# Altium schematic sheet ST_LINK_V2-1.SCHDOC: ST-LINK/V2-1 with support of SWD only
size A4; Author: A.B; CompanyName: STMicroelectronics; Organization: Microcontrollers Division; Address1: 12, Rue Jules HOROWITZ; Address2: 38019 Grenoble; Address3: FRANCE; DocumentNumber: MB1272; Revision: A-01; SheetNumber: 15; SheetTotal: 15; Project: STM32MP15-DISCO PI
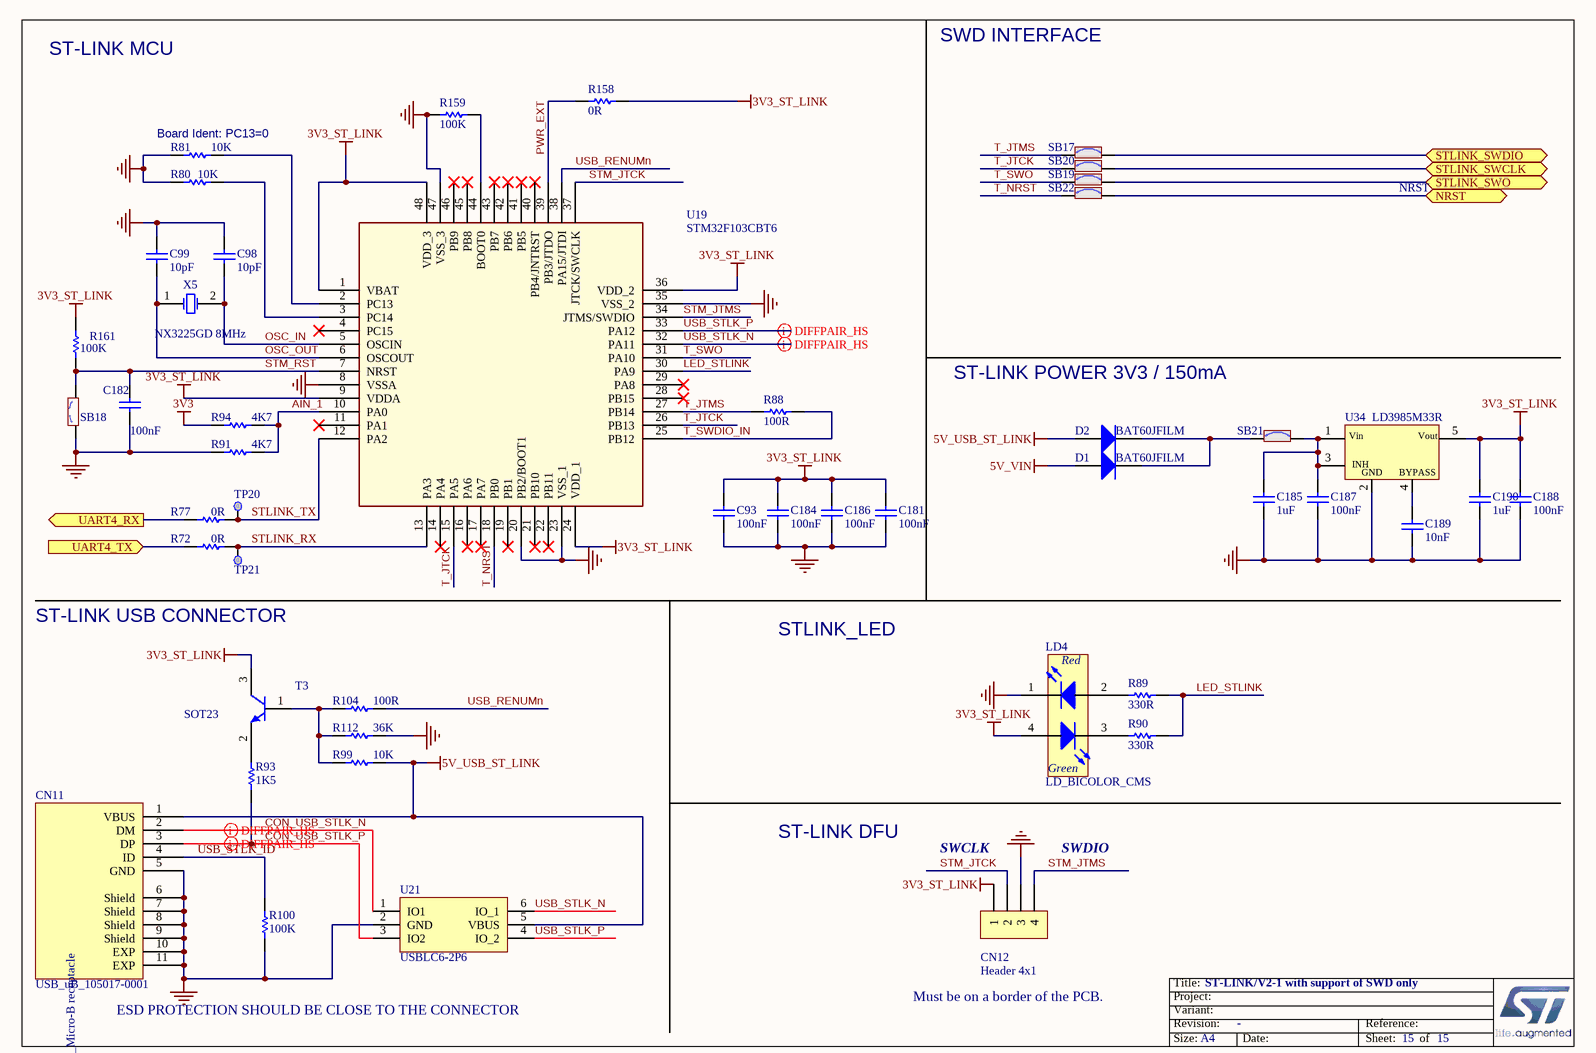
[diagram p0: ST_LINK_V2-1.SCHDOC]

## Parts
C93  value 100nF  [C0402]
C98  value 10pF  [C0402]
C99  value 10pF  [C0402]
C181  value 100nF  [C0402]
C182  value 100nF  [C0402]
C184  value 100nF  [C0402]
C185  value 1uF  [C0603]
C186  value 100nF  [C0402]
C187  value 100nF  [C0402]
C188  value 100nF  [C0402]
C189  value 10nF  [C0402]
C190  value 1uF  [C0603]
CN11  value USB_uB_105017-0001  [CON_USBMICROB_MOLEX_105017-0001_H2P90]
CN12  value Header 4x1  [CON_SAMTEC_TSW-104-07-G-S]
D1  value BAT60JFILM  [DIO_SOD323]
D2  value BAT60JFILM  [DIO_SOD323]
LD4  value LD_BICOLOR_CMS  [LED_BI-GR_HSMF-A201-A00J1]
R72  value 0R  [R0402]
R77  value 0R  [R0402]
R80  value 10K  [R0402]
R81  value 10K  [R0402]
R88  value 100R  [R0402]
R89  value 330R  [R0402]
R90  value 330R  [R0402]
R91  value 4K7  [R0402]
R93  value 1K5  [R0402]
R94  value 4K7  [R0402]
R99  value 10K  [R0402]
R100  value 100K  [R0402]
R104  value 100R  [R0402]
R112  value 36K  [R0402]
R158  value 0R  [R0402]
R159  value 100K  [R0402]
R161  value 100K  [R0402]
SB17  (no value)  [SOLDER-BRIDGE_R0603-0R]
SB18  (no value)  [SOLDER-BRIDGE_R0603-0R]
SB19  (no value)  [SOLDER-BRIDGE_R0603-0R]
SB20  (no value)  [SOLDER-BRIDGE_R0603-0R]
SB21  (no value)  [SOLDER-BRIDGE_R0603-0R]
SB22  (no value)  [SOLDER-BRIDGE_R0603-0R]
T3  value SOT23  [NPN_SOT23]
TP20  Test Point  [TP_SMD_1MM]  (value not drawn)  (no BOM)
TP21  Test Point  [TP_SMD_1MM]  (value not drawn)  (no BOM)
U19  value STM32F103CBT6  [ICC_LQFP48_7X7_P050]
U21  value USBLC6-2P6  [ESD_SOT666]
U34  value LD3985M33R  [REG_SOT23-5L]
X5  value NX3225GD 8MHz  [CRY_NX3225GD_2P]

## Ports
NRST (bidir), STLINK_SWCLK, STLINK_SWDIO, STLINK_SWO, UART4_RX (out), UART4_TX (in)

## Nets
3V3: R94.1
3V3_ST_LINK: C93.2 C181.2 C184.2 C186.2 C188.2 C190.2 CN12.1 LD4.4(YellowGreen_anode) R158.2 R161.2 T3.3(C) U19.1(VBAT) U19.9(VDDA) U19.24(VDD_1) U19.36(VDD_2) U19.48(VDD_3) U34.5(Vout)
5V_USB_ST_LINK: CN11.1(VBUS) D2.1(A) R99.1 U21.5(VBUS)
5V_VIN: D1.1(A)
GND: C93.1 C98.2 C99.2 C181.1 C182.1 C184.1 C185.2 C186.1 C187.1 C188.1 C189.1 C190.1 CN11.5(GND) CN11.6(Shield) CN11.7(Shield) CN11.8(Shield) CN11.9(Shield) CN11.10(EXP) CN11.11(EXP) CN12.3 LD4.1(RED_cathode) R80.1 R81.2 R91.1 R100.1 R112.1 R159.1 SB18.1 U19.8(VSSA) U19.20(PB2/BOOT1) U19.23(VSS_1) U19.35(VSS_2) U19.47(VSS_3) U21.2(GND) U34.2(GND)
AIN_1: R91.2 R94.2 U19.10(PA0)
CON_USB_STLK_N: CN11.2(DM) U21.1(IO1)
CON_USB_STLK_P: CN11.3(DP) R93.1 U21.3(IO2)
LED_STLINK: R89.2 R90.2 U19.30(PA9)
NRST: SB22.2 ; port NRST
OSC_IN: C98.1 U19.5(OSCIN) X5.2(OSC2)
OSC_OUT: C99.1 U19.6(OSCOUT) X5.1(OSC1)
PWR_EXT: R158.1 U19.39(PB3/JTDO)
STLINK_RX: R72.2 TP21.1 U19.13(PA3)
STLINK_SWCLK: SB20.2 ; port STLINK_SWCLK
STLINK_SWDIO: SB17.2 ; port STLINK_SWDIO
STLINK_SWO: SB19.2 ; port STLINK_SWO
STLINK_TX: R77.1 TP20.1 U19.12(PA2)
STM_JTCK: CN12.2 U19.37(JTCK/SWCLK)
STM_JTMS: CN12.4 U19.34(JTMS/SWDIO)
STM_RST: C182.2 R161.1 SB18.2 U19.7(NRST)
T_JTCK: SB20.1 U19.15(PA5) U19.26(PB13)
T_JTMS: R88.1 SB17.1 U19.27(PB14)
T_NRST: SB22.1 U19.18(PB0)
T_SWDIO_IN: R88.2 U19.25(PB12)
T_SWO: SB19.1 U19.31(PA10)
UART4_RX: R77.2 ; port UART4_RX
UART4_TX: R72.1 ; port UART4_TX
USB_RENUMn: R104.2 U19.38(PA15/JTDI)
USB_STLK_ID: CN11.4(ID) R100.2
USB_STLK_N: U19.32(PA11) U21.6(IO_1)
USB_STLK_P: U19.33(PA12) U21.4(IO_2)
NetC185_1: C185.1 C187.2 SB21.2 U34.1(Vin) U34.3(CE)
NetC189_2: C189.2 U34.4(BYPASS)
NetD1_2: D1.2(K) D2.2(K) SB21.1
NetLD4_2: LD4.2(Red_anode) R89.1
NetLD4_3: LD4.3(YellowGreen_cathode) R90.1
NetR80_2: R80.2 U19.3(PC14)
NetR81_1: R81.1 U19.2(PC13)
NetR93_2: R93.2 T3.2(E)
NetR99_2: R99.2 R104.1 R112.2 T3.1(B)
NetR159_2: R159.2 U19.44(BOOT0)

Not connected (* = marked no-connect by the designer): U19 4(PC15)* 11(PA1)* 14(PA4)* 16(PA6)* 17(PA7)* 19(PB1)* 21(PB10)* 22(PB11)* 28(PB15)* 29(PA8)* 40(PB4/JNTRST)* 41(PB5)* 42(PB6)* 43(PB7)* 45(PB8)* 46(PB9)*

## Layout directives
differential pair: CON_USB_STLK_N, CON_USB_STLK_P, USB_STLK_N, USB_STLK_P

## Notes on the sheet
- ST-LINK MCU
- SWD INTERFACE
- (near R81) Board Ident: PC13=0
- NRST
- ST-LINK POWER 3V3 / 150mA
- ST-LINK USB CONNECTOR
- STLINK_LED
- ST-LINK DFU
- SWCLK
- SWDIO
- Must be on a border of the PCB.
- (near CN11) ESD PROTECTION SHOULD BE CLOSE TO THE CONNECTOR

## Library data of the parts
C93 C181 C182 C184 C186-C188 = MCD-00006: Capacitor,100nF,16V,X7R,10%,0402; Manufacturer_Part_Number: CC0402KRX7R7BB104; Manufacturer: YAGEO; Alternate_Manufacturer: MURATA; Alternate_Manufacturer_Part_Number: GCM155R71C104KA55D; Provided_By: SUBCO; Initial_Board_Reference: mb1274
C98 C99 = MCD-00015: Capacitor,10pF,50V,NPO,5%,0402; Manufacturer_Part_Number: CC0402JRNPO9BN100; Manufacturer: YAGEO; Provided_By: SUBCO; Initial_Board_Reference: mb1274
C185 C190 = MCD-00238: Capacitor,1uF,6V3,X5R,10%,0603; Manufacturer_Part_Number: CC0603KRX5R5BB105; Manufacturer: YAGEO; Provided_By: SUBCO; Initial_Board_Reference: mb1319
C189 = MCD-00011: Capacitor,10nF,16V,X7R,10%,0402; Manufacturer_Part_Number: CC0402KRX7R7BB103; Manufacturer: YAGEO; Provided_By: SUBCO; Initial_Board_Reference: mb1274
CN11 = MCD-00028: USB-MICRO-B, 0.65mm, RA, SMT, Bottom Mount,; Manufacturer_Part_Number: 1050170001; Manufacturer: MOLEX; Part_Type: Connector; Provided_By: SUBCO; Initial_Board_Reference: mb1274
CN12 = MCD-00029: Header, 4x1, 2,54mm, VR, TH, Height 5.84mm/2.54mm; Manufacturer_Part_Number: TSW-104-07-x-S; Manufacturer: SAMTEC; Part_Type: Connector; Provided_By: SUBCO; Initial_Board_Reference: mb1274
D1 D2 = MCD-00034: BAT60JFILM; Manufacturer: STMICROELECTRONICS; Part_Type: Diode; BMS_Part_Number: 9151097; ECCN_US: EAR99; ECCN_EU: NEC; Provided_By: SUBCO with ST control; Initial_Board_Reference: mb1274
LD4 = MCD-00051: LED Bicolor; Manufacturer_Part_Number: HSMF-A201-A00J1; Manufacturer: AVAGO TECHNOLOGIES; Alternate_Manufacturer_Part_Number: LE-RGW35280; Alternate_Manufacturer: EVERLUCK; Part_Type: Display; ECCN_US: EAR99; ECCN_EU: NEC; Provided_By: SUBCO; Initial_Board_Reference: mb1274
R72 R77 R158 = MCD-00052: Resistor,0R,0402,5%,1/16W; Manufacturer_Part_Number: RC0402JR-070RL; Manufacturer: YAGEO; Provided_By: SUBCO; Initial_Board_Reference: mb1274
R80 R81 R99 = MCD-00053: Resistor,10K,0402,1%,1/16W; Manufacturer_Part_Number: RC0402FR-0710KL; Manufacturer: YAGEO; Provided_By: SUBCO; Initial_Board_Reference: mb1274
R88 R104 = MCD-00067: Resistor,100R,0402,1%,1/16W; Manufacturer_Part_Number: RC0402FR-07100RL; Manufacturer: YAGEO; Provided_By: SUBCO; Initial_Board_Reference: mb1274
R89 R90 = MCD-00062: Resistor,330R,0402,1%,1/16W; Manufacturer_Part_Number: RC0402FR-07330RL; Manufacturer: YAGEO; Provided_By: SUBCO; Initial_Board_Reference: mb1274
R91 R94 = MCD-00065: Resistor,4K7,0402,1%,1/16W; Manufacturer_Part_Number: RC0402FR-074K7L; Manufacturer: YAGEO; Alternate_Manufacturer_Part_Number: RT0402FRE074K7L; Provided_By: SUBCO; Initial_Board_Reference: mb1274
R93 = MCD-00068: Resistor,1K5,0402,1%,1/16W; Manufacturer_Part_Number: RC0402FR-071K5L; Manufacturer: YAGEO; Provided_By: SUBCO; Initial_Board_Reference: mb1274
R100 R159 R161 = MCD-00059: Resistor,100K,0402,1%,1/16W; Manufacturer_Part_Number: RC0402FR-07100KL; Manufacturer: YAGEO; Alternate_Manufacturer_Part_Number: RT0402FRE07100KL; Provided_By: SUBCO; Initial_Board_Reference: mb1274
R112 = MCD-00069: Resistor,36K,0402,1%,1/16W; Manufacturer_Part_Number: RC0402FR-0736KL; Manufacturer: YAGEO; Provided_By: SUBCO; Initial_Board_Reference: mb1274
SB17 SB19-SB22 = MCD-00071: Solder Bridge ON; Part_Type: Mechanical; Manufacturer: YAGEO; Manufacturer_Part_Number: RC0603JR-070RL; Provided_By: SUBCO; Initial_Board_Reference: mb1274
SB18 = MCD-00072: Solder Bridge OFF; Part_Type: Mechanical; Manufacturer: YAGEO; Manufacturer_Part_Number: RC0603JR-070RL; Provided_By: SUBCO; Initial_Board_Reference: mb1274
T3 = MCD-00073: NPN Bipolar Transistor; Manufacturer_Part_Number: BSR14; Manufacturer: ON SEMICONDUCTOR; Part_Type: IC; Alternate_Manufacturer_Part_Number: MMBT2222ALT1G / MMBT2222ALT3G; ECCN_US: EAR99; ECCN_EU: NEC; Provided_By: SUBCO; Initial_Board_Reference: mb1274
TP20 TP21 = MCD-00074: Test Point 1mm; Part_Type: Mechanical; Initial_Board_Reference: MB1274
U19 = MCD-00085: Medium-density performance line ARM-based 32-bit MCU with 128KB Flash; Manufacturer: STMICROELECTRONICS; Part_Type: IC; BMS_Part_Number: 9175111; ECCN_US: 3A991A2; ECCN_EU: NEC; Provided_By: SUBCO with ST control; Initial_Board_Reference: mb1274
U21 = MCD-00169: USB OTG FS ESD protection; Manufacturer: STMICROELECTRONICS; Part_Type: IC; BMS_Part_Number: 9151057; Provided_By: SUBCO with ST control; ECCN_US: EAR99; ECCN_EU: NEC; Initial_Board_Reference: MB1274
U34 = MCD-00086: Ultra low drop-low noise BiCMOS voltage, regulators low ESR capacitors compatible; Manufacturer: STMICROELECTRONICS; Part_Type: IC; BMS_Part_Number: 9176161; ECCN_US: EAR99; ECCN_EU: NEC; Provided_By: SUBCO with ST control; Initial_Board_Reference: mb1274
X5 = MCD-00092: Crystal 8Mhz, 8pF, -+50PPM, SMD; Manufacturer_Part_Number: NX3225GD 8MHz EXS00A-CG04874; Manufacturer: NDK; Part_Type: Crystal_Osc; BMS_Part_Number: 9157029; ECCN_US: EAR99; ECCN_EU: NEC; Provided_By: SUBCO; Initial_Board_Reference: mb1274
